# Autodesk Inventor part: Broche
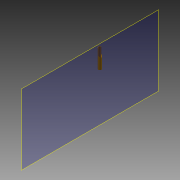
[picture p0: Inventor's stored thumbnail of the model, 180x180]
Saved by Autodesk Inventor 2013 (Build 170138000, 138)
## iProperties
Created: 2013-12
Part Number: Broche
Material: Laiton, jaune doux, soudé
Document SubType Name: Modeling
Designer: leininger-65460
Density: 1 g/cm^3
Author: leininger-65460
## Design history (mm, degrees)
sketch "Esquisse1"
  geometry: C1 r 0.5 at (0, -3.5); C2 r 0.4 at (0, -3.5); 1 further point
  constraints: 2 centre point, 1 coincident
  dimensions: "d5" = 1 diameter of C1; "d6" = 0.8 diameter of C2
extrude "Extrusion1" new body sketch "Esquisse1" distance "d3" = 6; taper "d4" = 0 deg
node "Plan de construction1"
sketch "Esquisse2"
  geometry: L1 (16, -19.6)-(17, -19.6) reference; L2 (17, -13.6)-(17, -19.6) reference; L3 (15.994, -19.6)-(17, -19.6); L4 (17, -19.6)-(17, -17.588); L5 (15.994, -17.588)-(15.994, -19.6); A1 r 0.503 centre (16.497, -17.588) between (17, -17.588) and (15.994, -17.588); 1 further point
  constraints: 6 end point, 2 point on circle, 2 point on line, 1 centre point, 1 horizontal, 1 parallel, 1 perpendicular
extrude "Extrusion2" cut sketch "Esquisse2" distance "d7" = 10; taper "d8" = 0 deg
node "Solide1"
